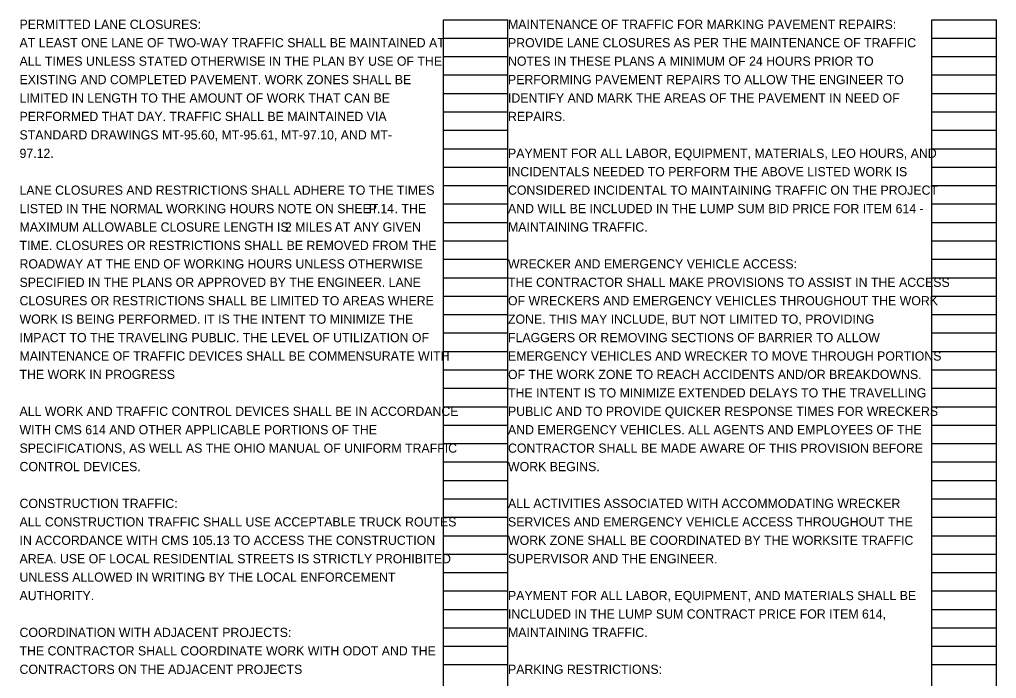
# Model space of a CAD drawing. Extents: x 0 to 37668, y -5 to 18949.
# Drawn here: x 37638.8 to 37653.64, y 18907.67 to 18917.68 of the extents above; entities that cross this region are included whole.
import ezdxf

# ---------------------------------------------------------------- set-up
doc = ezdxf.new("R2010")
doc.units = 0
doc.layers.add('SH_Data', color=7, linetype='Continuous')
doc.layers.add('SH_Text', color=7, linetype='Continuous')

msp = doc.modelspace()

# ---------------------------------------------------------------- linework, layer by layer
at = {"layer": 'SH_Data'}
for p, q in [((37645.241, 18897.522), (37645.241, 18917.682)), ((37645.241, 18917.682), (37646.221, 18917.682)), ((37646.221, 18897.522), (37646.221, 18917.682)), ((37652.661, 18897.522), (37652.661, 18917.682)), ((37652.661, 18917.682), (37653.641, 18917.682)), ((37653.641, 18897.522), (37653.641, 18917.682)), ((37645.241, 18917.402), (37646.221, 18917.402)), ((37652.661, 18917.402), (37653.641, 18917.402)), ((37645.241, 18917.122), (37646.221, 18917.122)), ((37652.661, 18917.122), (37653.641, 18917.122)), ((37645.241, 18916.842), (37646.221, 18916.842)), ((37652.661, 18916.842), (37653.641, 18916.842)), ((37645.241, 18916.562), (37646.221, 18916.562)), ((37652.661, 18916.562), (37653.641, 18916.562)), ((37645.241, 18916.282), (37646.221, 18916.282)), ((37652.661, 18916.282), (37653.641, 18916.282)), ((37645.241, 18916.002), (37646.221, 18916.002)), ((37652.661, 18916.002), (37653.641, 18916.002)), ((37645.241, 18915.722), (37646.221, 18915.722)), ((37652.661, 18915.722), (37653.641, 18915.722)), ((37645.241, 18915.442), (37646.221, 18915.442)), ((37652.661, 18915.442), (37653.641, 18915.442)), ((37645.241, 18915.162), (37646.221, 18915.162)), ((37652.661, 18915.162), (37653.641, 18915.162)), ((37645.241, 18914.882), (37646.221, 18914.882)), ((37652.661, 18914.882), (37653.641, 18914.882)), ((37645.241, 18914.602), (37646.221, 18914.602)), ((37652.661, 18914.602), (37653.641, 18914.602)), ((37645.241, 18914.322), (37646.221, 18914.322)), ((37652.661, 18914.322), (37653.641, 18914.322)), ((37645.241, 18914.042), (37646.221, 18914.042)), ((37652.661, 18914.042), (37653.641, 18914.042)), ((37645.241, 18913.762), (37646.221, 18913.762)), ((37652.661, 18913.762), (37653.641, 18913.762)), ((37645.241, 18913.482), (37646.221, 18913.482)), ((37652.661, 18913.482), (37653.641, 18913.482)), ((37645.241, 18913.202), (37646.221, 18913.202)), ((37652.661, 18913.202), (37653.641, 18913.202)), ((37645.241, 18912.922), (37646.221, 18912.922)), ((37652.661, 18912.922), (37653.641, 18912.922)), ((37645.241, 18912.642), (37646.221, 18912.642)), ((37652.661, 18912.642), (37653.641, 18912.642)), ((37645.241, 18912.362), (37646.221, 18912.362)), ((37652.661, 18912.362), (37653.641, 18912.362)), ((37645.241, 18912.082), (37646.221, 18912.082)), ((37652.661, 18912.082), (37653.641, 18912.082)), ((37645.241, 18911.802), (37646.221, 18911.802)), ((37652.661, 18911.802), (37653.641, 18911.802)), ((37645.241, 18911.522), (37646.221, 18911.522)), ((37652.661, 18911.522), (37653.641, 18911.522)), ((37645.241, 18911.242), (37646.221, 18911.242)), ((37652.661, 18911.242), (37653.641, 18911.242)), ((37645.241, 18910.962), (37646.221, 18910.962)), ((37652.661, 18910.962), (37653.641, 18910.962)), ((37645.241, 18910.682), (37646.221, 18910.682)), ((37652.661, 18910.682), (37653.641, 18910.682)), ((37645.241, 18910.402), (37646.221, 18910.402)), ((37652.661, 18910.402), (37653.641, 18910.402)), ((37645.241, 18910.122), (37646.221, 18910.122)), ((37652.661, 18910.122), (37653.641, 18910.122)), ((37645.241, 18909.842), (37646.221, 18909.842)), ((37652.661, 18909.842), (37653.641, 18909.842)), ((37645.241, 18909.562), (37646.221, 18909.562)), ((37652.661, 18909.562), (37653.641, 18909.562)), ((37645.241, 18909.282), (37646.221, 18909.282)), ((37652.661, 18909.282), (37653.641, 18909.282)), ((37645.241, 18909.002), (37646.221, 18909.002)), ((37652.661, 18909.002), (37653.641, 18909.002)), ((37645.241, 18908.722), (37646.221, 18908.722)), ((37652.661, 18908.722), (37653.641, 18908.722)), ((37645.241, 18908.442), (37646.221, 18908.442)), ((37652.661, 18908.442), (37653.641, 18908.442)), ((37645.241, 18908.162), (37646.221, 18908.162)), ((37652.661, 18908.162), (37653.641, 18908.162)), ((37645.241, 18907.882), (37646.221, 18907.882)), ((37652.661, 18907.882), (37653.641, 18907.882))]:
    msp.add_line(p, q, dxfattribs=at)

# ---------------------------------------------------------------- texts
at = {"layer": 'SH_Text'}
for s, p in [('PERMITTED LANE CLOSURES:', (37638.801, 18917.542)), ('MAINTENANCE OF TRAFFIC FOR MARKING PAVEMENT REPAIRS:', (37646.221, 18917.542)), ('AT LEAST ONE LANE OF TWO-WAY TRAFFIC SHALL BE MAINTAINED AT ', (37638.801, 18917.262)), ('PROVIDE LANE CLOSURES AS PER THE MAINTENANCE OF TRAFFIC ', (37646.221, 18917.262)), ('ALL TIMES UNLESS STATED OTHERWISE IN THE PLAN BY USE OF THE ', (37638.801, 18916.982)), ('NOTES IN THESE PLANS A MINIMUM OF 24 HOURS PRIOR TO ', (37646.221, 18916.982)), ('EXISTING AND COMPLETED PAVEMENT. WORK ZONES SHALL BE ', (37638.801, 18916.702)), ('PERFORMING PAVEMENT REPAIRS TO ALLOW THE ENGINEER TO ', (37646.221, 18916.702)), ('LIMITED IN LENGTH TO THE AMOUNT OF WORK THAT CAN BE ', (37638.801, 18916.422)), ('IDENTIFY AND MARK THE AREAS OF THE PAVEMENT IN NEED OF ', (37646.221, 18916.422)), ('PERFORMED THAT DAY. TRAFFIC SHALL BE MAINTAINED VIA ', (37638.801, 18916.142)), ('REPAIRS.', (37646.221, 18916.142)), ('STANDARD DRAWINGS MT-95.60, MT-95.61, MT-97.10, AND MT-', (37638.801, 18915.862)), ('97.12. ', (37638.801, 18915.582)), ('PAYMENT FOR ALL LABOR, EQUIPMENT, MATERIALS, LEO HOURS, AND ', (37646.221, 18915.582)), ('INCIDENTALS NEEDED TO PERFORM THE ABOVE LISTED WORK IS ', (37646.221, 18915.302)), ('LANE CLOSURES AND RESTRICTIONS SHALL ADHERE TO THE TIMES ', (37638.801, 18915.022)), ('CONSIDERED INCIDENTAL TO MAINTAINING TRAFFIC ON THE PROJECT ', (37646.221, 18915.022)), ('LISTED IN THE NORMAL WORKING HOURS NOTE ON SHEET ', (37638.801, 18914.742)), ('P.14', (37644.105, 18914.742)), ('. ', (37644.498, 18914.742)), ('THE ', (37644.604, 18914.742)), ('AND WILL BE INCLUDED IN THE LUMP SUM BID PRICE FOR ITEM 614 - ', (37646.221, 18914.742)), ('MAXIMUM ALLOWABLE CLOSURE LENGTH IS ', (37638.801, 18914.462)), ('2 MILES', (37642.832, 18914.462)), (' AT ANY GIVEN ', (37643.536, 18914.462)), ('MAINTAINING TRAFFIC.', (37646.221, 18914.462)), ('TIME. CLOSURES OR RESTRICTIONS SHALL BE REMOVED FROM THE ', (37638.801, 18914.182)), ('ROADWAY AT THE END OF WORKING HOURS UNLESS OTHERWISE ', (37638.801, 18913.902)), ('WRECKER AND EMERGENCY VEHICLE ACCESS:', (37646.221, 18913.902)), ('SPECIFIED IN THE PLANS OR APPROVED BY THE ENGINEER. LANE ', (37638.801, 18913.622)), ('THE CONTRACTOR SHALL MAKE PROVISIONS TO ASSIST IN THE ACCESS ', (37646.221, 18913.622)), ('CLOSURES OR RESTRICTIONS SHALL BE LIMITED TO AREAS WHERE ', (37638.801, 18913.342)), ('OF WRECKERS AND EMERGENCY VEHICLES THROUGHOUT THE WORK ', (37646.221, 18913.342)), ('WORK IS BEING PERFORMED. IT IS THE INTENT TO MINIMIZE THE ', (37638.801, 18913.062)), ('ZONE. THIS MAY INCLUDE, BUT NOT LIMITED TO, PROVIDING ', (37646.221, 18913.062)), ('IMPACT TO THE TRAVELING PUBLIC. THE LEVEL OF UTILIZATION OF ', (37638.801, 18912.782)), ('FLAGGERS OR REMOVING SECTIONS OF BARRIER TO ALLOW ', (37646.221, 18912.782)), ('MAINTENANCE OF TRAFFIC DEVICES SHALL BE COMMENSURATE WITH ', (37638.801, 18912.502)), ('EMERGENCY VEHICLES AND WRECKER TO MOVE THROUGH PORTIONS ', (37646.221, 18912.502)), ('THE WORK IN PROGRESS', (37638.801, 18912.222)), ('OF THE WORK ZONE TO REACH ACCIDENTS AND/OR BREAKDOWNS. ', (37646.221, 18912.222)), ('THE INTENT IS TO MINIMIZE EXTENDED DELAYS TO THE TRAVELLING ', (37646.221, 18911.942)), ('ALL WORK AND TRAFFIC CONTROL DEVICES SHALL BE IN ACCORDANCE ', (37638.801, 18911.662)), ('PUBLIC AND TO PROVIDE QUICKER RESPONSE TIMES FOR WRECKERS ', (37646.221, 18911.662)), ('WITH CMS 614 AND OTHER APPLICABLE PORTIONS OF THE ', (37638.801, 18911.382)), ('AND EMERGENCY VEHICLES. ALL AGENTS AND EMPLOYEES OF THE ', (37646.221, 18911.382)), ('SPECIFICATIONS, AS WELL AS THE OHIO MANUAL OF UNIFORM TRAFFIC ', (37638.801, 18911.102)), ('CONTRACTOR SHALL BE MADE AWARE OF THIS PROVISION BEFORE ', (37646.221, 18911.102)), ('CONTROL DEVICES.', (37638.801, 18910.822)), ('WORK BEGINS.', (37646.221, 18910.822)), ('CONSTRUCTION TRAFFIC:', (37638.801, 18910.262)), ('ALL ACTIVITIES ASSOCIATED WITH ACCOMMODATING WRECKER ', (37646.221, 18910.262)), ('ALL CONSTRUCTION TRAFFIC SHALL USE ACCEPTABLE TRUCK ROUTES ', (37638.801, 18909.982)), ('SERVICES AND EMERGENCY VEHICLE ACCESS THROUGHOUT THE ', (37646.221, 18909.982)), ('IN ACCORDANCE WITH CMS 105.13 TO ACCESS THE CONSTRUCTION ', (37638.801, 18909.702)), ('WORK ZONE SHALL BE COORDINATED BY THE WORKSITE TRAFFIC ', (37646.221, 18909.702)), ('AREA. USE OF LOCAL RESIDENTIAL STREETS IS STRICTLY PROHIBITED ', (37638.801, 18909.422)), ('SUPERVISOR AND THE ENGINEER.', (37646.221, 18909.422)), ('UNLESS ALLOWED IN WRITING BY THE LOCAL ENFORCEMENT ', (37638.801, 18909.142)), ('AUTHORITY.', (37638.801, 18908.862)), ('PAYMENT FOR ALL LABOR, EQUIPMENT, AND MATERIALS SHALL BE ', (37646.221, 18908.862)), ('INCLUDED IN THE LUMP SUM CONTRACT PRICE FOR ITEM 614, ', (37646.221, 18908.582)), ('COORDINATION WITH ADJACENT PROJECTS:', (37638.801, 18908.302)), ('MAINTAINING TRAFFIC.', (37646.221, 18908.302)), ('THE CONTRACTOR SHALL COORDINATE WORK WITH ODOT AND THE ', (37638.801, 18908.022)), ('CONTRACTORS ON THE ADJACENT PROJECTS', (37638.801, 18907.742)), (': ', (37642.762, 18907.742)), ('PARKING RESTRICTIONS:', (37646.221, 18907.742))]:
    msp.add_text(s, height=0.14, dxfattribs=at).set_placement(p)

doc.saveas('drawing.dxf')
